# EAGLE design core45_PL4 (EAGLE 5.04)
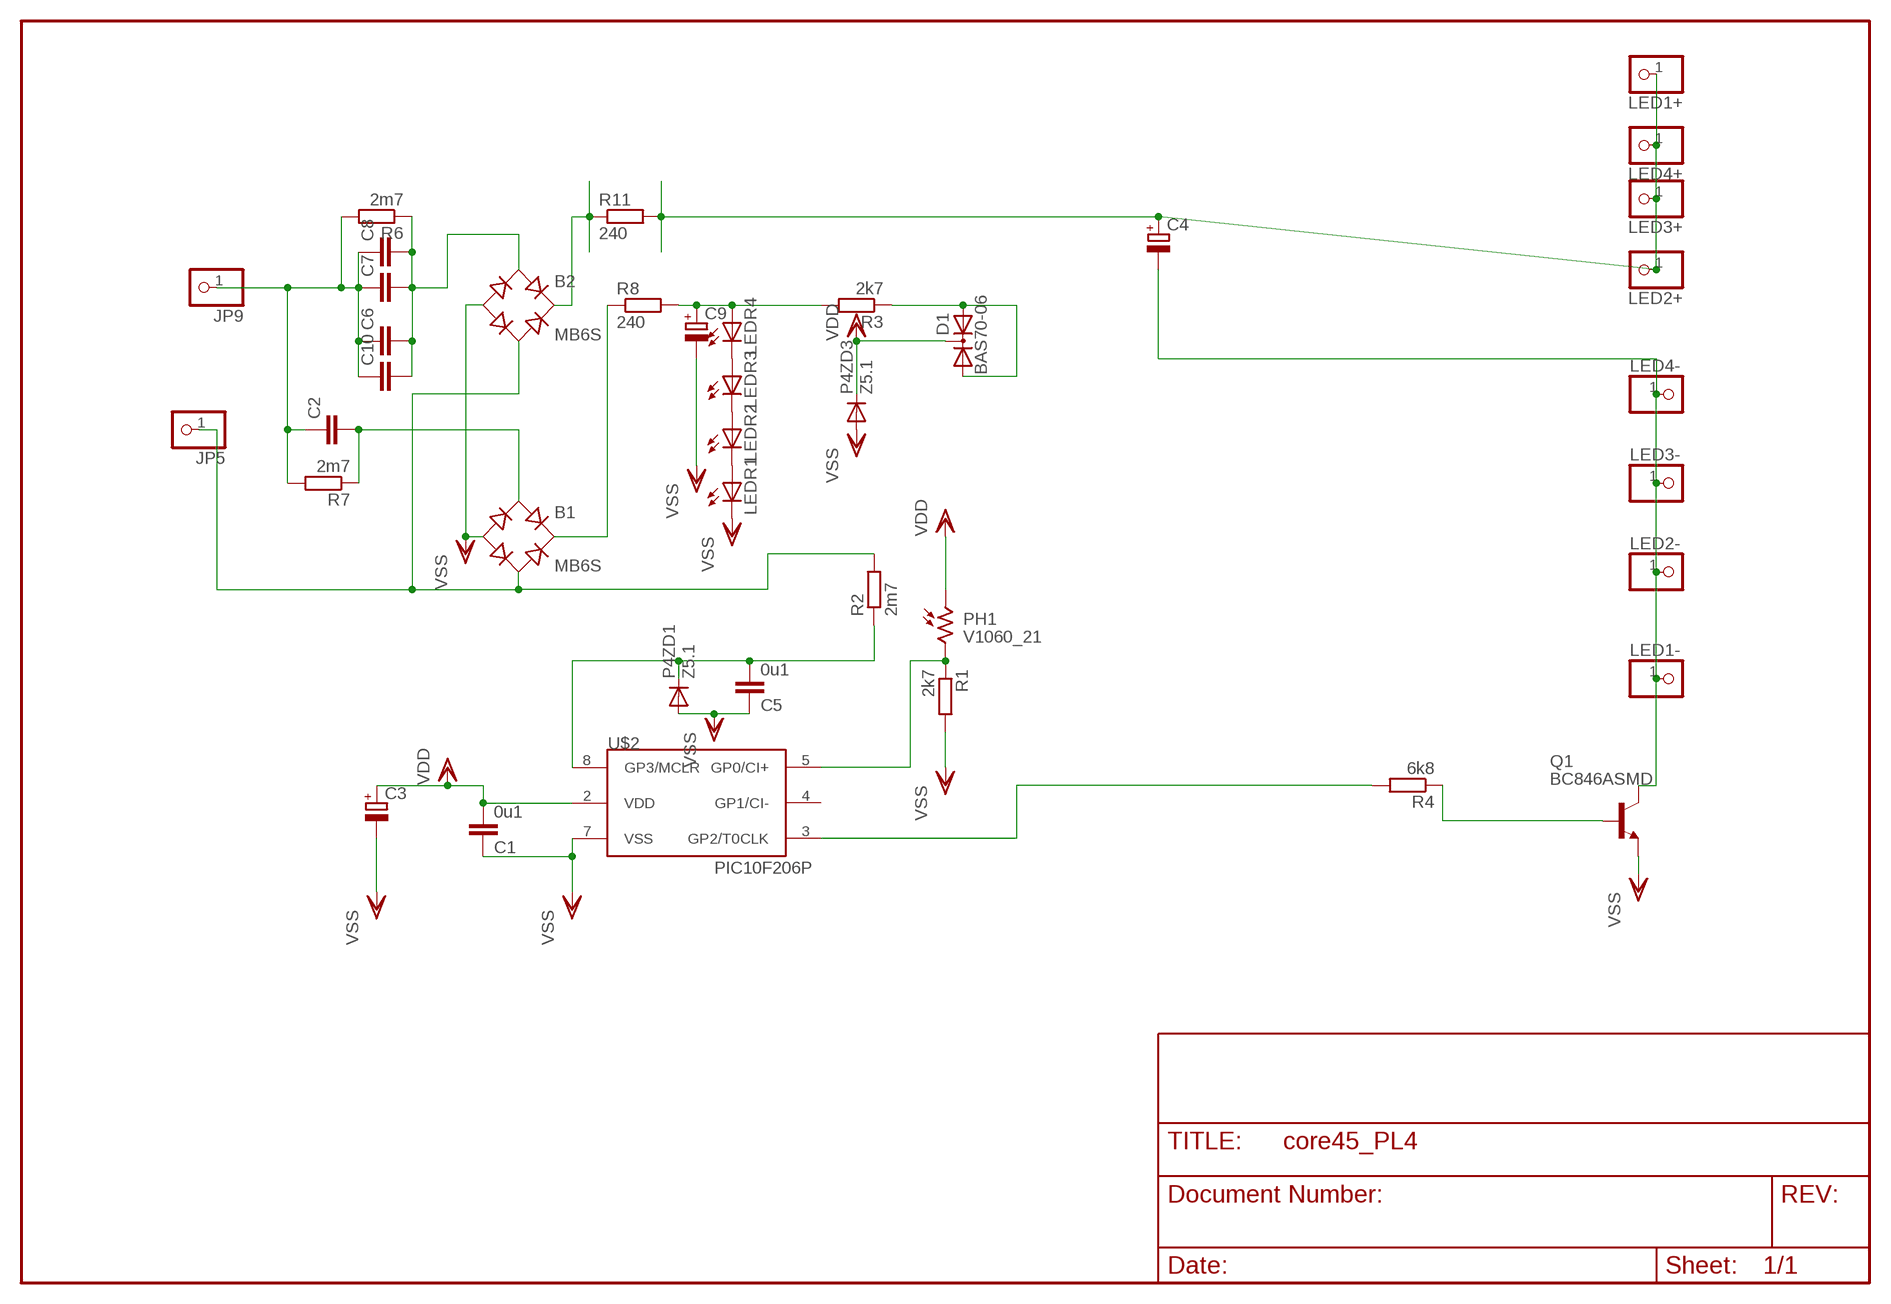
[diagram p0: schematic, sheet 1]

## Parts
B1  MB6S  [SOIC-4]
B2  MB6S  [SOIC-4]
C1  0u1  C-EUC1206  [C1206]
C2  C-EU075-052X106  [C075-052X106]
C3  CPOL-EU5-13  [2,5-5-FLAT]
C4  CPOL-EUTT5D11L  [TT5D11L]
C5  0u1  C-EUC1206  [C1206]
C6  C-EU150-064X183  [C150-064X183]
C7  C-EU150-054X183  [C150-054X183]
C8  C-EU150-054X183  [C150-054X183]
C9  CPOL-EUTT5D11L  [TT5D11L]
C10  C-EU150-064X183  [C150-064X183]
D1  BAS70-06  [SOT23]
JP5  PINHD-1X1  [1X01]
JP9  PINHD-1X1  [1X01]
LED1+  PINHD-1X1  [1X01]
LED1-  PINHD-1X1  [1X01]
LED2+  PINHD-1X1  [1X01]
LED2-  PINHD-1X1  [1X01]
LED3+  PINHD-1X1  [1X01]
LED3-  PINHD-1X1  [1X01]
LED4+  PINHD-1X1  [1X01]
LED4-  PINHD-1X1  [1X01]
LEDR1  LEDP-LCC-4  [P-LCC-4]
LEDR2  LEDP-LCC-4  [P-LCC-4]
LEDR3  LEDP-LCC-4  [P-LCC-4]
LEDR4  LEDP-LCC-4  [P-LCC-4]
P4ZD1  Z5.1  DIODE-MINIMELF  [MINIMELF]
P4ZD3  Z5.1  DIODE-MINIMELF  [MINIMELF]
PH1  V1060_21  [TO-5_V10]
Q1  BC846ASMD  [SOT23]
R1  2k7  R-EU_R0805  [R0805]
R2  2m7  R-EU_R1206  [R1206]
R3  2k7  R-EU_R0805  [R0805]
R4  6k8  R-EU_R0805  [R0805]
R6  2m7  R-EU_R1206  [R1206]
R7  2m7  R-EU_R1206  [R1206]
R8  240  R-EU_0204/5  [0204/5]
R11  240  R-EU_0204/5  [0204/5]
U$2  PIC10F206P  [DIL8]

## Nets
AC1: B1.~2(AC2) B2.~2(AC2) JP5.1 R2.2
AC2: C2.1 C6.1 C7.1 C8.1 C10.1 JP9.1 R6.2 R7.2
CBIG: B2.~1(AC1) C6.2 C7.2 C8.2 C10.2 R6.1
D+: C4.+ LED1+.1 LED2+.1 LED3+.1 LED4+.1 R11.2
D-: C4.- LED1-.1 LED2-.1 LED3-.1 LED4-.1 Q1.3(C)
DR+: C9.+ LEDR4.A R3.2 R8.2
N$1: C5.2 P4ZD1.C R2.1 U$2.8(GP3/MCLR)
N$3: LEDR3.A LEDR4.C@4(C)
N$5: D1.1(A1) D1.2(A2) R3.1
N$6: LEDR2.A LEDR3.C@4(C)
N$7: LEDR1.A LEDR2.C@4(C)
N$8: B1.~1(AC1) C2.2 R7.1
N$11: B2.+ R11.1
N$12: Q1.1(B) R4.1
N$15: R4.2 U$2.3(GP2/T0CLK)
N$17: PH1.2 R1.1 U$2.5(GP0/CI+)
RECDR+: B1.+ R8.1
VDD: C1.2 C3.+ D1.3(C) P4ZD3.C PH1.1 U$2.2(VDD)
VSS: B1.- B2.- C1.1 C3.- C5.1 C9.- LEDR1.C@4(C) P4ZD1.A P4ZD3.A Q1.2(E) R1.2 U$2.7(VSS)
Unconnected: U$2.4(GP1/CI-)

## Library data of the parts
B1 B2 = rectifier:MB*S: Bridge Rectifier Source: http://www.fairchildsemi.com/ds/MB/MB6S.pdf
C1 C5 = rcl:C-EU: CAPACITOR, European symbol
C2 C6-C8 C10 = rcl-2:C-EU: CAPACITOR, European symbol
C3 C4 C9 = rcl-2:CPOL-EU: POLARIZED CAPACITOR, European symbol
D1 = diode:BAS70-06: Silicon Schottky Diodes General-purpose diode for high-speed switching
JP5 JP9 LED1+ LED1- LED2+ LED2- LED3+ LED3- LED4+ LED4- = pinhead(2):PINHD-1X1: PIN HEADER
LEDR1-LEDR4 = led(3):LED: LED
P4ZD1 P4ZD3 = diode:DIODE-: DIODE
PH1 = photo-elements:?1060*: Sensor Street Light control
Q1 = transistor-npn:BC846*: NPN Transistor
R1-R4 R6-R8 R11 = rcl-2:R-EU_: RESISTOR, European symbol
U$2 = microchip-3:PIC10F2*: uPC nW 0,25/0,5k Program Flash memory Comparator

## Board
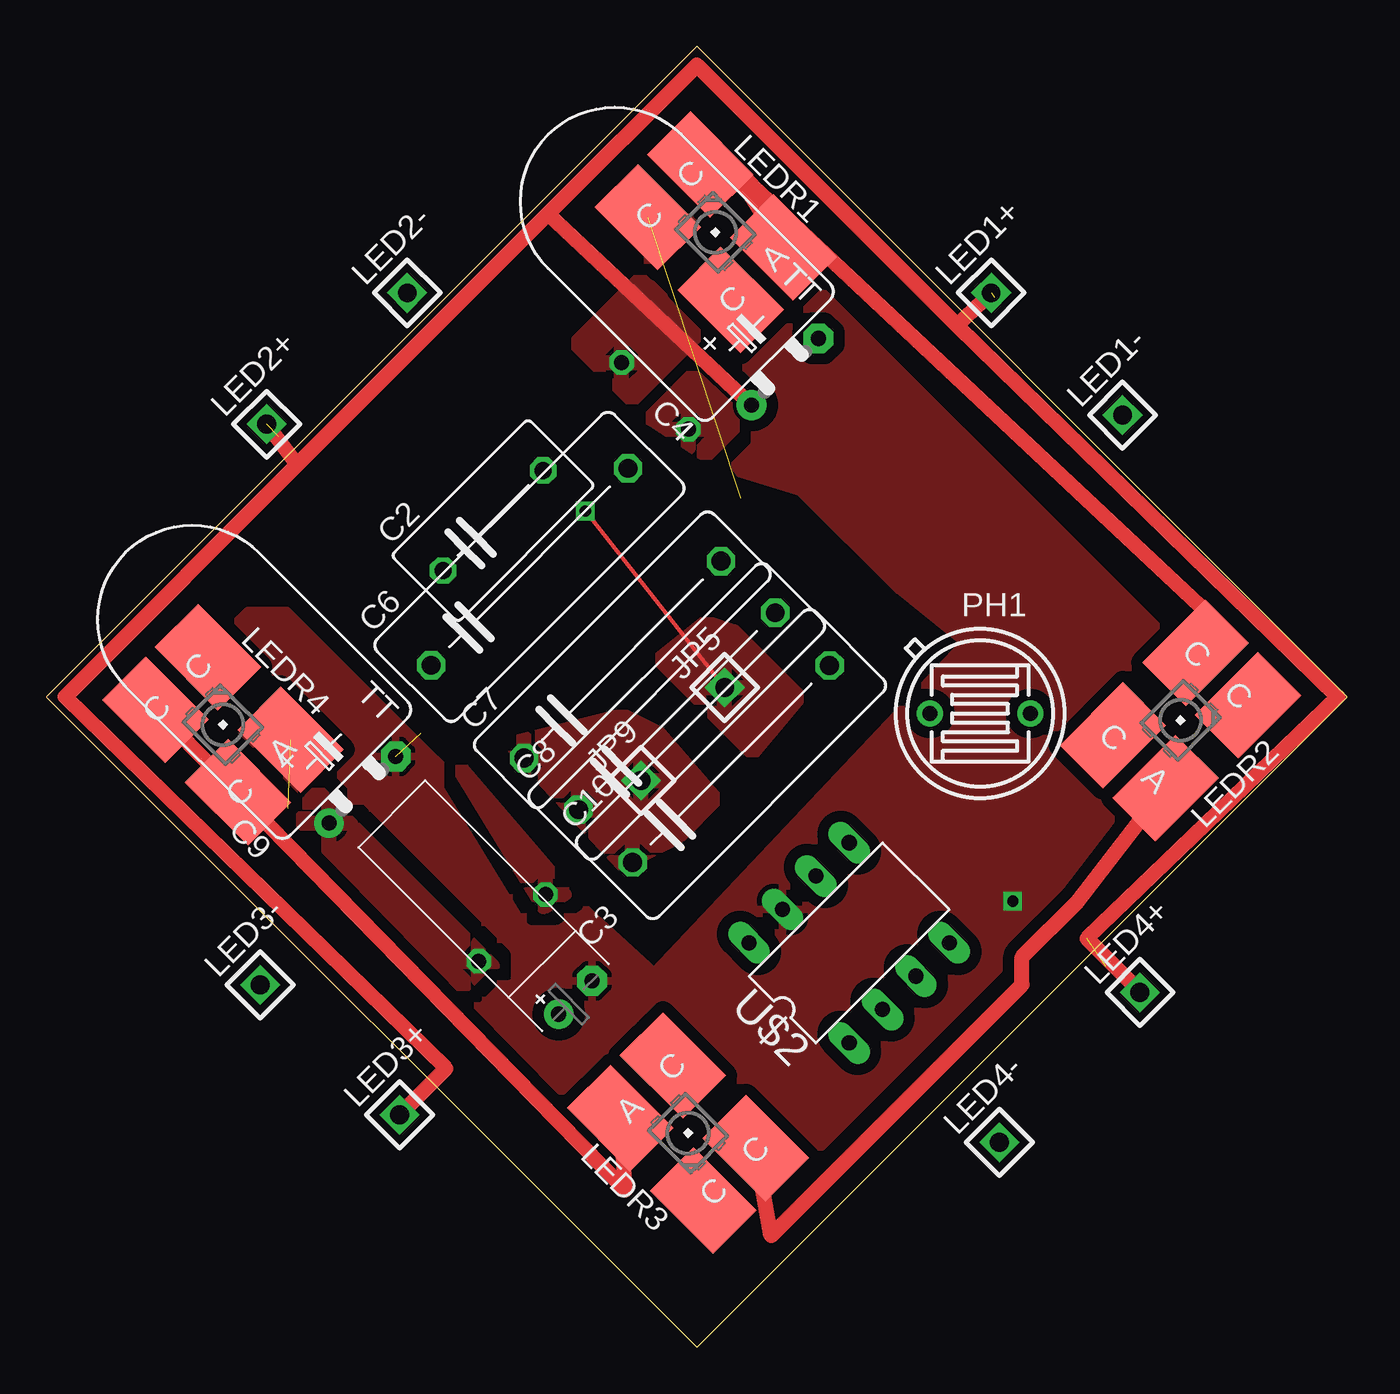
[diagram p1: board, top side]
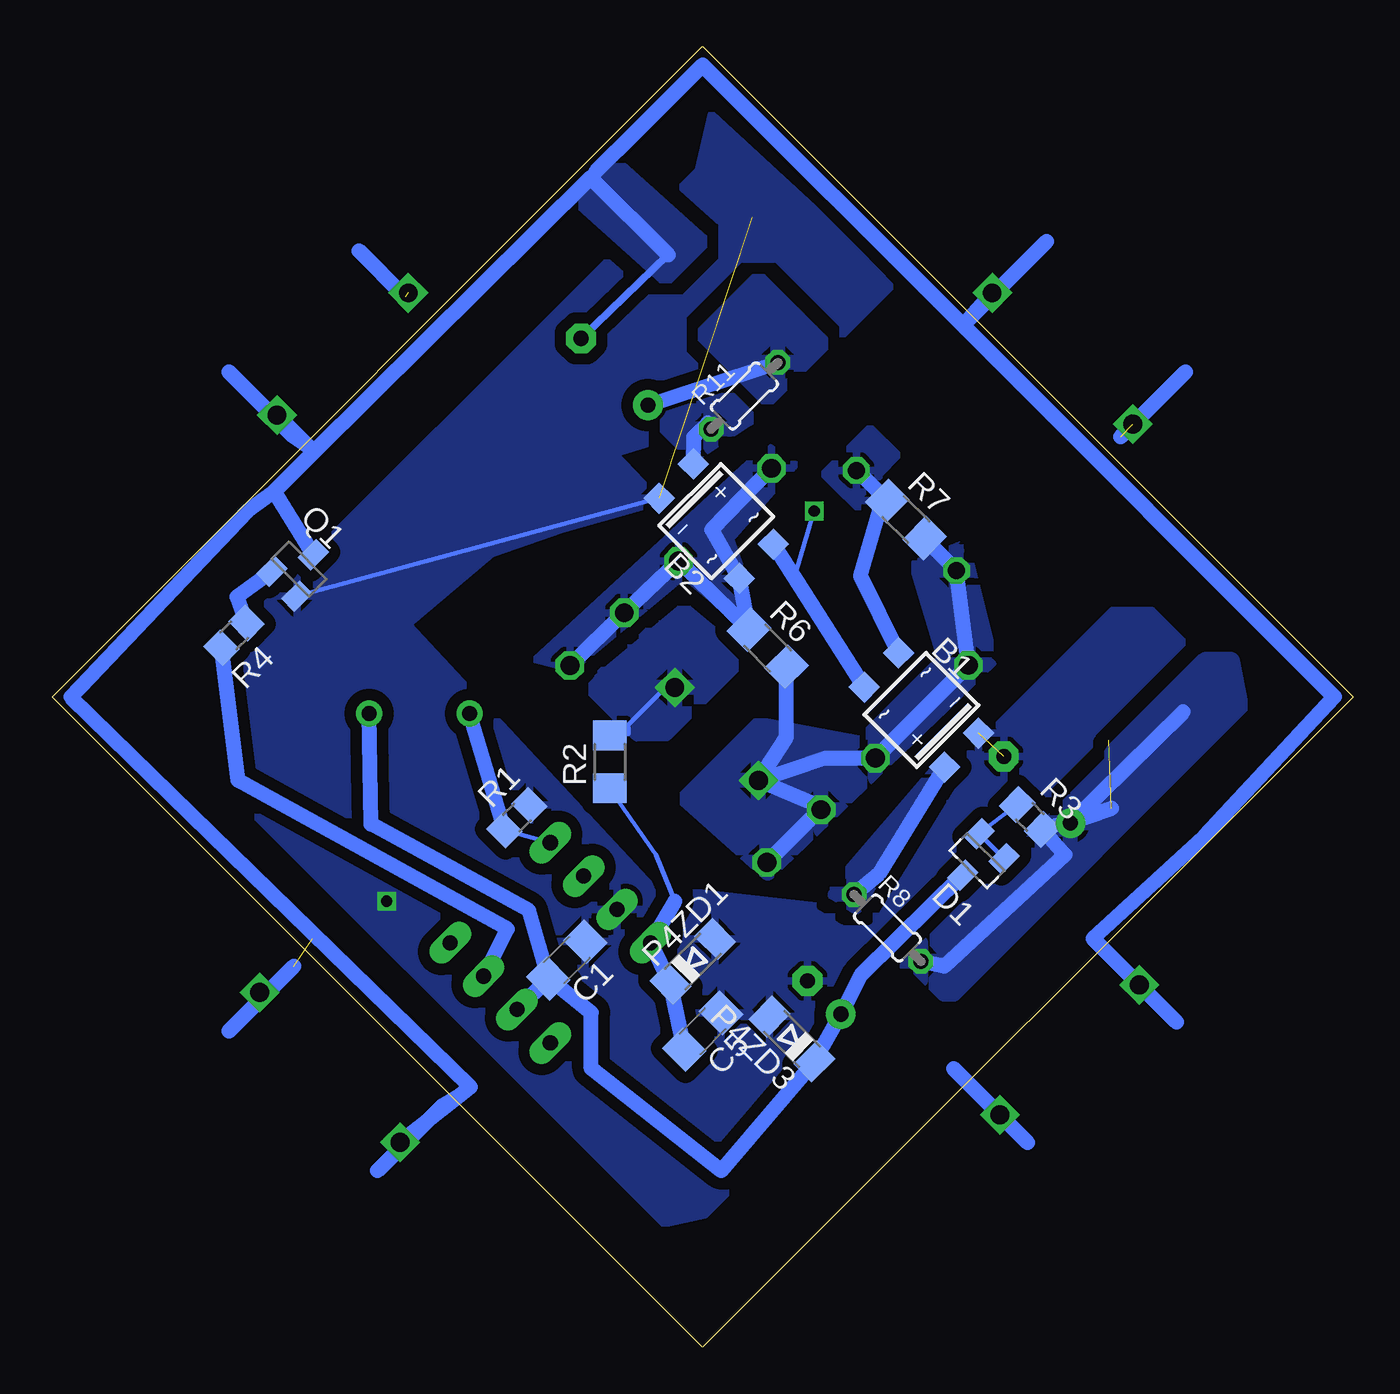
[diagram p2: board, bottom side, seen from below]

Size 70 x 70 mm. Coordinates in mm from the lower left corner, seen from the top.
Outline: 35,0 70,35 35,70 0,35 35,0
Copper layers (1*16): Top 0.035mm / dielectric 1.5mm / Bottom 0.035mm
Design rules "default": minimum track width 10mil, minimum drill 24mil, track to track 8mil, track to pad 8mil, pad to pad 8mil, via to via 8mil, smd to smd 8mil, copper to edge 40mil, drill to drill 8mil, minimum pad ring 10mil, minimum via ring 8mil, stop-mask expansion 4mil, vias tented up to drill 0mil, thermal gap 10mil

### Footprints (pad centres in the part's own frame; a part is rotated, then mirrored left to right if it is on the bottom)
SOIC-4 = smd 1.2 x 1.2: + 1.3,3.05; - -1.3,3.05; ~1 -1.3,-3.05; ~2 1.3,-3.05
C1206 = smd 1.6 x 1.8: 1 -1.4,0; 2 1.4,0
C075-052X106 = drill 0.914 octagon: 1 -3.81,0; 2 3.81,0
2,5-5-FLAT = drill 0.813 pad 1.6 round: + -1.27,0 | drill 0.813 pad 1.6 octagon: - 1.27,0
TT5D11L = drill 0.813 pad 1.6 round: + -2.54,0 | drill 0.813 pad 1.6 octagon: - 2.54,0
C150-064X183 = drill 1.016 octagon: 1 -7.493,0; 2 7.493,0
C150-054X183 = drill 1.016 octagon: 1 -7.493,0; 2 7.493,0
SOT23 = smd 1 x 1.4: 1 -0.95,-1.1; 2 0.95,-1.1; 3 0,1.1
1X01 = drill 1.016 square: 1 0,0
P-LCC-4 = smd 3.3 x 4.8: A -2,3.15; C@1 -2,-3.15; C@3 2,3.15; C@4 2,-3.15
MINIMELF = smd 1.4 x 1.8: A 1.7,0; C -1.7,0
TO-5_V10 = drill 0.8 pad 1.4 round: 1 -2.7,0; 2 2.7,0
R0805 = smd 1.3 x 1.5: 1 -0.95,0; 2 0.95,0
R1206 = smd 1.6 x 1.803: 1 -1.422,0; 2 1.422,0
0204/5 = drill 0.813 octagon: 1 -2.54,0; 2 2.54,0
DIL8 = drill 0.813 long: 1 -3.81,-3.81; 2 -1.27,-3.81; 3 1.27,-3.81; 4 3.81,-3.81; 5 3.81,3.81; 6 1.27,3.81; 7 -1.27,3.81; 8 -3.81,3.81

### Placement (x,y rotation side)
B1  23.22,34.29 225 bottom
B2  34.27,44.46 45 bottom
C1  42.31,20.84 225 bottom
C2  24.03,44.49 45 top
C3  28.46,18.82 45 top
C4  39.74,52.49 45 top
C5  35,17 225 bottom
C6  26,42 45 top
C7  31,37 45 top
C8  33.92,34.22 45 top
C9  17,30 45 top
C10  36.84,31.39 45 top
D1  20.23,26.19 135 bottom
JP5  36.5,35.5 45 top
JP9  32,30.5 45 top
LED1+  50.84,56.74 45 top
LED1-  57.91,50.17 45 top
LED2+  11.85,49.67 45 top
LED2-  19.42,56.74 45 top
LED3+  19,12.5 45 top
LED3-  11.5,19.5 45 top
LED4+  58.85,19.1 45 top
LED4-  51.28,11.03 45 top
LEDR1  36,60 225 top
LEDR2  61.03,33.74 135 top
LEDR3  34.53,11.53 45 top
LEDR4  9.5,33.5 225 top
P4ZD1  35.53,20.76 45 bottom
P4ZD3  30.2,16.59 135 bottom
PH1  50.25,34.11 180 top
Q1  56.73,41.87 315 bottom
R1  45,28.5 45 bottom
R2  40,31.5 90 bottom
R3  17.4,28.54 315 bottom
R4  60.22,38.31 225 bottom
R6  31.5,37.62 315 bottom
R7  24.06,44.55 315 bottom
R8  25.06,22.56 315 bottom
R11  32.75,51.2 45 bottom
U$2  43.2,21.76 45 top

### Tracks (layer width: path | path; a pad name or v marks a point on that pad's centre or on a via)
AC1  (via drill 0.6)
  Top 0.254: v29,45 JP5.1
  Bottom 0.254: R2.2 39,33 39,33.5 37,35.5 JP5.1 | 30.07,41.45 v29,45
  Bottom 0.813: B1.~2 30.07,41.45 B2.~2
  pour Bottom (isolate 0.61, rank 2): 33,37 37,33 38.5,33 41,35.5 36.5,40 36,40
  pour Top (isolate 0.61): 33,37 38,32 40.5,35 37,38.5 35.5,39
AC2
  Bottom 0.813: JP9.1 28.41,31.7 C7.1 C6.1 C2.1 R7.2 | JP9.1 28.89,29.19 C8.1 28.71,28.93 C10.1 | JP9.1 30.49,32.83 R6.2
  pour Bottom (isolate 0.813, rank 2): 21,43 23.5,42 22,37 26.5,32.5 32,33.5 36,29.5 31.5,25.5 19.5,37
  pour Top (isolate 0.813, rank 2): 25,32.5 31,34 33,33 36,29.5 34,27.5 31,26
CBIG
  Bottom 0.813: C6.2 34.5,44 B2.~1 R6.1 C7.2 C8.2 C10.2
  pour Bottom (isolate 0.61): 31.5,48.5 44,37 42,36.5 36,41.5 33,39 33,42 33.5,43.5 30,47.5
D+  (3 unrouted)
  Top 0.406: 14,48 13.5,47.5 | 58.85,19.15 LED4+.1
  Top 0.813: 27,61 C4.+ | 27,61 14,48 1,35 21.5,15 LED3+.1 | 13.5,47.5 LED2+.1 | 58.85,19.15 56,22 69.5,35 49,55 | 49,55 LED1+.1 | 49,55 35,69 27,61
  Bottom 0.813: C4.+ R11.2 | 51,56.5 53.5,59 | 60.5,17 57,20.5 | 12.5,49 9,52.5
  pour Bottom (isolate 0.61): 32,57.5 28.5,54 31.5,51 35,54.5
  pour Top (isolate 0.61): 32,57.5 28.5,54 31.5,51 35,54.5
D-
  Bottom 0.406: 40.76,63.25 41.02,62.95 | 36.86,58.79 C4.-
  Bottom 0.813: 55.91,48.19 56.11,48.39 | 56.11,48.39 LED1-.1 | 55.91,48.19 58.05,46.05 | 58.05,46.05 Q1.3 | 55.91,48.19 41.02,62.95 36.86,58.79 | 21,55 35,69 38.5,65.5 40.76,63.25 | 21,55 1,35 8,27.5 14,22 13,21 | 13,21 LED3-.1 | 48.05,13.57 47.5,14 69,35 59.5,45 58.05,46.05 | 48.05,13.57 LED4-.1 | 19.5,56.5 16.5,59.5 | 19.5,56.5 20,56 | 9.5,17.5 13,21 | 52.5,9.5 49,13 48.05,13.57 | 60.5,52.5 57,49 56.11,48.39 | 21,55 LED2-.1 | 21,55 19.5,56.5
  pour Bottom (isolate 0.61): 35,59.5 37,57.5 42,62 40,64
DR+  (1 unrouted)
  Bottom 0.813: R8.2 22,20.5 15.5,26.5 R3.2 13,29 C9.+ 9.14,34.19
  pour Bottom (isolate 0.61): 6.5,37 8,37 13,32 13,31.5 24,20.5 23.5,20.5 22,19 21.5,19 6,34.5
  pour Top (isolate 0.61): 6.5,37 8,37 13,32 13,31.5 24,20.5 23.5,20.5 22,19 21.5,19 6,34.5
N$1
  Bottom 0.254: R2.1 37.5,26.5 36.5,24
  Bottom 0.813: 36.5,24 U$2.8 P4ZD1.C C5.2
N$3
  Top 0.813: LEDR3.A 31.15,8.45 LEDR4.C@4
N$5
  Bottom 0.254: R3.1 D1.2 D1.1
N$6
  Top 0.813: LEDR3.C@4 39,6 52.5,19.5 52.5,21 55.5,24 LEDR2.A
N$7
  Top 0.813: LEDR1.A 36.9,63.6 38,62.5 62.5,39.5 LEDR2.C@4
N$8
  Bottom 0.813: C2.2 R7.1 25.5,45 26.5,41.5 B1.~1
  pour Bottom (isolate 0.61): 25.5,47 24.5,48 26,49.5 28.5,47 26,44.5
N$10
  Bottom 0.813: 17.5,11 21.5,15
N$11
  Bottom 0.813: B2.+ 35.47,48.99 34.72,49.74 R11.1
  pour Bottom: 32.5,50 35.5,53 36,53 38,51 38,50.5 35.5,48
  pour Top: 32.5,50 35.5,53 36,53 38,51 38,50.5 35.5,48
N$12
  Bottom 0.813: Q1.1 60.05,40.39 R4.1
N$15
  Bottom 0.813: U$2.3 45.5,22.5 60,30.5 R4.2
N$17
  Bottom 0.254: U$2.5 R1.1
  Bottom 0.813: R1.1 PH1.2
RECDR+
  Bottom 0.813: B1.+ 25.5,25.5 R8.1
  pour Bottom (isolate 0.61): 22,31.5 26.75,23.7 28,24.5
  pour Top (isolate 0.61): 22,31.5 26.75,23.7 28,24.5
VDD
  Bottom 0.813: C1.2 41,18 41,15 34,9.5 P4ZD3.C C3.+ 26.5,20 24.5,22 D1.3 | C1.2 44.35,23.5 52.85,28.15 PH1.1 | C1.2 U$2.2
VSS  (via drill 0.6)  (2 unrouted)
  Bottom 0.254: B2.- Q1.2
  other vias: 52,24
  pour Bottom (isolate 0.61, rank 5): 6.59,35.41 10.84,39.66 12.96,39.66 28.87,23.75 37.7,24.75 50.84,38.89 46.34,42.72 42.54,44.02 37.29,45.52 39.73,48.08 31.23,50.7 24.87,57.07 28.37,60.69 34.53,66.34 35.23,63.34 63.16,35.41 64.66,34.21 37.09,6.63 34.88,7.13
  pour Top (isolate 0.61, rank 5): 5.74,34.71 10.84,39.66 12.96,39.66 28.87,23.75 32.7,20.25 49.34,37.89 45.84,40.72 40.54,46.02 37.29,47.02 36.23,48.58 35.23,49.2 28.87,55.57 28.87,57.69 34.53,63.34 35.23,63.34 63.16,35.41 64.06,33.11 36.49,5.53 34.03,6.43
